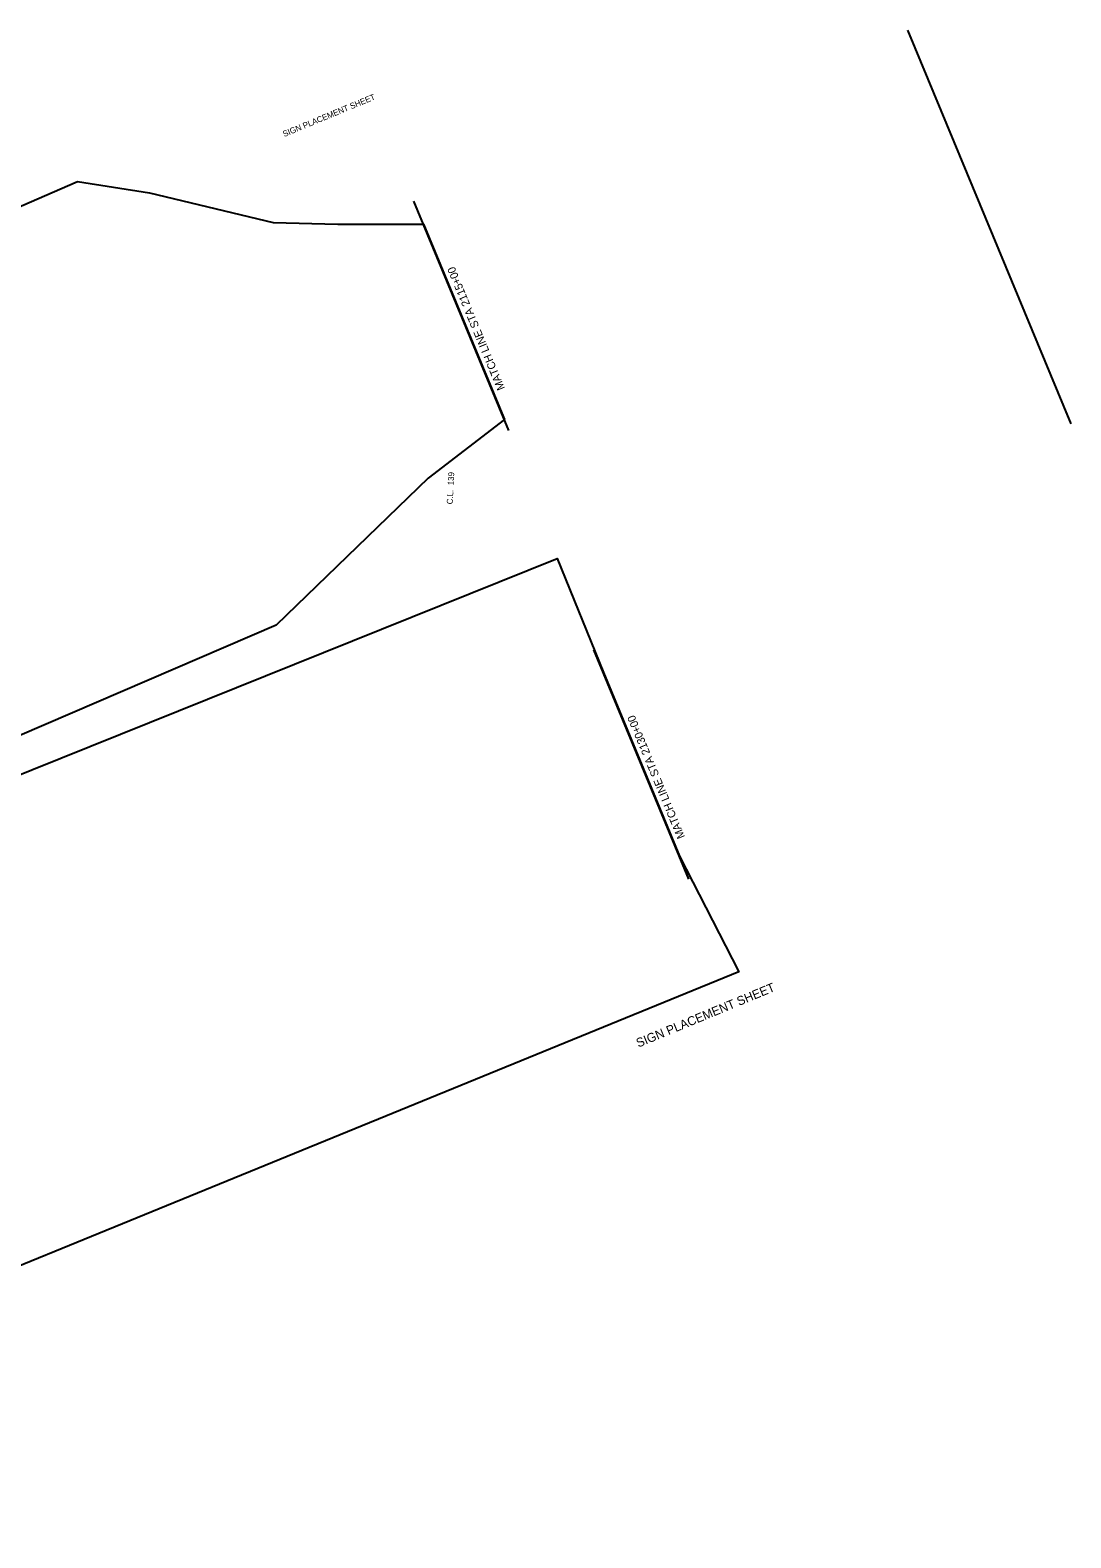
# Model space of a CAD drawing. Extents: x 1716142 to 1718238, y 765201 to 766730.
# Drawn here: x 1717190 to 1718238, y 765211 to 766730 of the extents above; entities that cross this region are included whole.
import ezdxf

# ---------------------------------------------------------------- set-up
doc = ezdxf.new("R2010")
doc.units = 0
for name, color, linetype in [('R_6IN_DASHED-RPM_WHITE_ENHANCED THERMO', 7, 'Continuous'), ('R_6IN_DBL_YELLOW_REFLECTORIZED_PAINT', 7, 'Continuous'), ('R_6IN_DBL_YELLOW_THERMOPLASTIC', 7, 'Continuous'), ('R_6IN_SOLID_YELLOW_ENHANCED THERMO', 7, 'Continuous'), ('R_RPM_TYPE 2_RED-WHITE', 7, 'Continuous')]:
    doc.layers.add(name, color=color, linetype=linetype)

msp = doc.modelspace()

# ---------------------------------------------------------------- linework, layer by layer
at = {"layer": 'R_6IN_DBL_YELLOW_REFLECTORIZED_PAINT'}
for p, q in [((1717671.7, 766326.7), (1717576, 766557.7)), ((1717852.9, 765874.8), (1717757.2, 766105.8))]:
    msp.add_line(p, q, dxfattribs=at)
at = {"layer": 'R_RPM_TYPE 2_RED-WHITE'}
msp.add_line((1718073.2, 766730.1), (1718237.6, 766333.3), dxfattribs=at)
for points in [[(1716327.3, 765652.6), (1716141.5, 766101.2), (1717237.3, 766577.7), (1717309.6, 766566), (1717434.3, 766536.2), (1717499.4, 766534.7), (1717585.6, 766534.6), (1717662.1, 766349.8), (1717667.2, 766337.9), (1717590.3, 766278.6), (1717437.4, 766130.6)], [(1716508.6, 765211), (1716457.5, 765323.9), (1716381, 765508.7), (1716327.7, 765626.8), (1716388.1, 765590.2), (1716468.3, 765623.9), (1716486.6, 765701.2), (1717720.1, 766197.7), (1717766.8, 766082.7), (1717843.3, 765897.9), (1717903.1, 765781.4)]]:
    msp.add_lwpolyline(points, close=True, dxfattribs=at)

# ---------------------------------------------------------------- texts
at = {"layer": 'R_6IN_DASHED-RPM_WHITE_ENHANCED THERMO'}
msp.add_text('C.L.  139', height=6, rotation=87.0742, dxfattribs=at).set_placement((1717615, 766252.2))
at = {"layer": 'R_6IN_DBL_YELLOW_REFLECTORIZED_PAINT'}
for s, p in [('MATCH LINE STA 2115+00', (1717667.8, 766369.2)), ('MATCH LINE STA 2130+00', (1717849.1, 765917.3))]:
    msp.add_text(s, height=8, rotation=112.5, dxfattribs=at).set_placement(p)
at = {"layer": 'R_6IN_DBL_YELLOW_THERMOPLASTIC'}
msp.add_text('SIGN PLACEMENT SHEET', height=9, rotation=22.5, dxfattribs=at).set_placement((1717802.1, 765704.9))
at = {"layer": 'R_6IN_SOLID_YELLOW_ENHANCED THERMO'}
msp.add_text('SIGN PLACEMENT SHEET', height=6, rotation=22.5, dxfattribs=at).set_placement((1717445.4, 766622.3))

doc.saveas('drawing.dxf')
